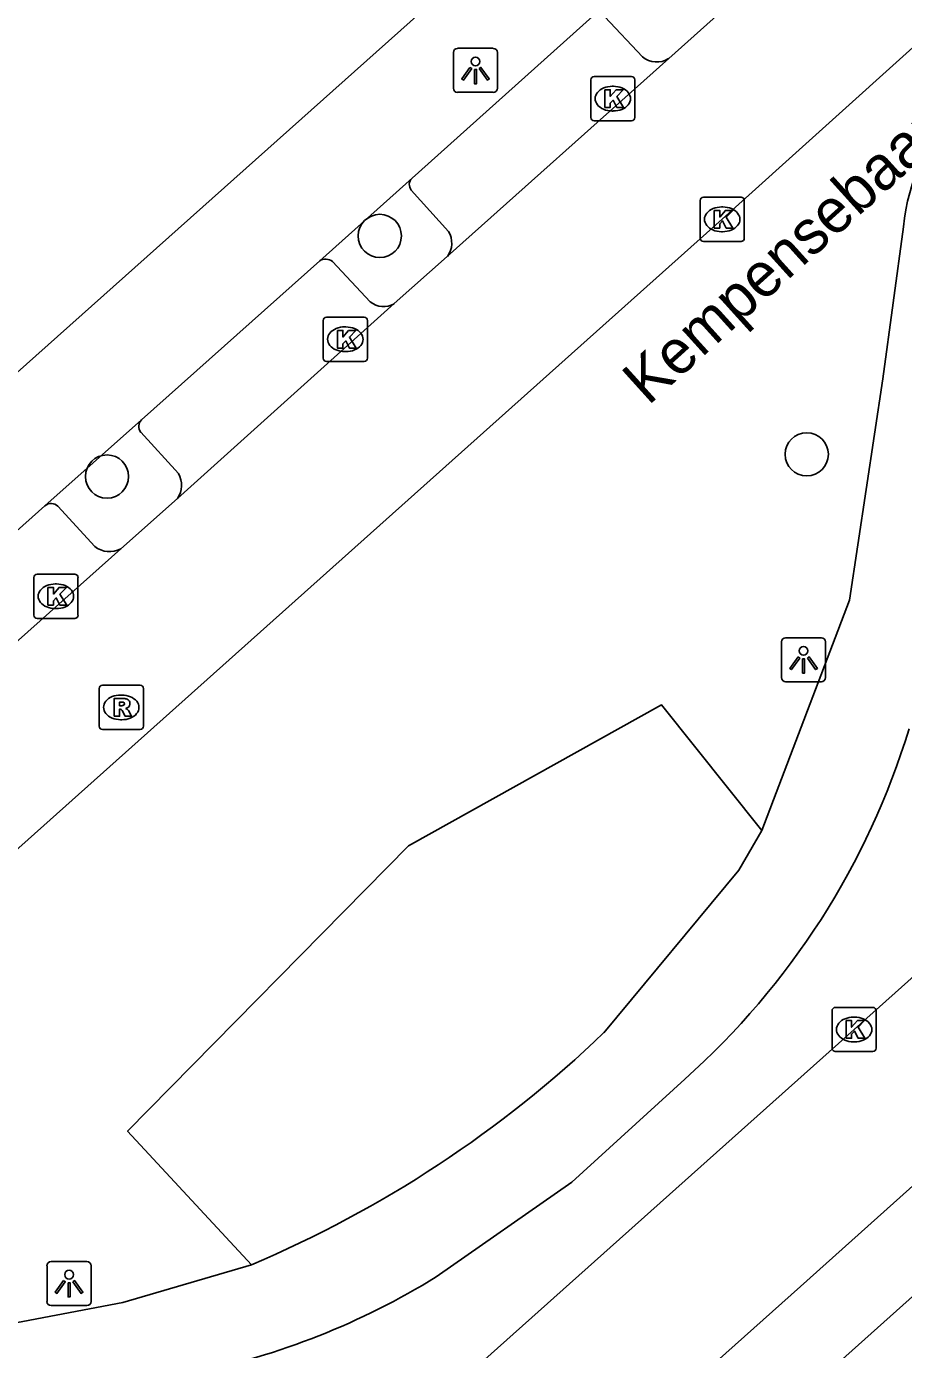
# Model space of a CAD drawing. Extents: x 162172 to 163187, y 382874 to 383684.
# Drawn here: x 162616.09 to 162635.94, y 383205.06 to 383235.01 of the extents above; entities that cross this region are included whole.
import ezdxf

# ---------------------------------------------------------------- set-up
doc = ezdxf.new("R2010")
doc.units = 0
for name, color, linetype in [('IMGEO_Berm_groen', 7, 'Continuous'), ('IMGEO_Boom', 7, 'Continuous'), ('IMGEO_Kolk', 7, 'Continuous'), ('IMGEO_Lichtpunt', 7, 'Continuous'), ('IMGEO_Openbare_ruimte_label', 7, 'Continuous'), ('IMGEO_Rijbaan_lokaal_open', 7, 'Continuous'), ('IMGEO_Rioolput', 7, 'Continuous'), ('IMGEO_Voetpad_gesloten', 7, 'Continuous'), ('IMGEO_Voetpad_open', 7, 'Continuous')]:
    doc.layers.add(name, color=color, linetype=linetype)

msp = doc.modelspace()

# ---------------------------------------------------------------- linework, layer by layer
at = {"layer": 'IMGEO_Berm_groen'}
msp.add_lwpolyline([(162632.733, 383216.809), (162630.462, 383219.659), (162624.74, 383216.468), (162618.378, 383210.002), (162621.186, 383206.981)], dxfattribs=at)
at = {"layer": 'IMGEO_Boom'}
for centre in [(162624.089, 383230.272), (162633.752, 383225.328), (162617.914, 383224.825)]:
    msp.add_circle(centre, 0.489, dxfattribs=at)
at = {"layer": 'IMGEO_Kolk'}
for p, q in [((162628.862, 383232.954), (162628.862, 383233.806)), ((162628.937, 383233.88), (162629.789, 383233.88)), ((162629.863, 383233.806), (162629.863, 383232.954)), ((162629.35, 383233.66), (162629.375, 383233.66)), ((162629.373, 383233.1), (162629.348, 383233.1)), ((162629.789, 383232.88), (162628.937, 383232.88)), ((162631.413, 383231.148), (162632.265, 383231.148)), ((162631.338, 383230.222), (162631.338, 383231.074)), ((162631.826, 383230.928), (162631.851, 383230.928)), ((162632.339, 383231.074), (162632.339, 383230.222)), ((162631.849, 383230.368), (162631.824, 383230.368)), ((162632.265, 383230.148), (162631.413, 383230.148)), ((162622.883, 383228.433), (162623.735, 383228.433)), ((162622.808, 383227.507), (162622.808, 383228.359)), ((162623.296, 383228.213), (162623.321, 383228.213)), ((162623.809, 383228.359), (162623.809, 383227.507)), ((162623.319, 383227.653), (162623.294, 383227.653)), ((162623.735, 383227.433), (162622.883, 383227.433)), ((162616.256, 383221.688), (162616.256, 383222.54)), ((162616.331, 383222.614), (162617.183, 383222.614)), ((162617.257, 383222.54), (162617.257, 383221.688)), ((162616.744, 383222.394), (162616.769, 383222.394)), ((162616.767, 383221.834), (162616.742, 383221.834)), ((162617.183, 383221.614), (162616.331, 383221.614)), ((162634.324, 383211.882), (162634.324, 383212.734)), ((162634.399, 383212.808), (162635.251, 383212.808)), ((162634.812, 383212.588), (162634.837, 383212.588)), ((162635.325, 383212.734), (162635.325, 383211.882)), ((162634.835, 383212.028), (162634.81, 383212.028)), ((162635.251, 383211.808), (162634.399, 383211.808))]:
    msp.add_line(p, q, dxfattribs=at)
for points in [[(162628.862, 383232.954), (162628.862, 383233.806)], [(162628.937, 383233.88), (162629.789, 383233.88)], [(162629.863, 383233.806), (162629.863, 383232.954)], [(162629.183, 383233.58), (162629.306, 383233.58), (162629.306, 383233.429), (162629.436, 383233.58), (162629.6, 383233.58), (162629.454, 383233.429), (162629.607, 383233.18), (162629.455, 383233.18), (162629.37, 383233.344), (162629.306, 383233.277), (162629.306, 383233.18), (162629.183, 383233.18), (162629.183, 383233.58)], [(162629.789, 383232.88), (162628.937, 383232.88)], [(162631.413, 383231.148), (162632.265, 383231.148)], [(162631.338, 383230.222), (162631.338, 383231.074)], [(162631.659, 383230.848), (162631.782, 383230.848), (162631.782, 383230.697), (162631.912, 383230.848), (162632.076, 383230.848), (162631.93, 383230.697), (162632.083, 383230.448), (162631.931, 383230.448), (162631.846, 383230.612), (162631.782, 383230.545), (162631.782, 383230.448), (162631.659, 383230.448), (162631.659, 383230.848)], [(162632.339, 383231.074), (162632.339, 383230.222)], [(162632.265, 383230.148), (162631.413, 383230.148)], [(162622.883, 383228.433), (162623.735, 383228.433)], [(162622.808, 383227.507), (162622.808, 383228.359)], [(162623.129, 383228.133), (162623.252, 383228.133), (162623.252, 383227.982), (162623.382, 383228.133), (162623.546, 383228.133), (162623.4, 383227.982), (162623.553, 383227.733), (162623.401, 383227.733), (162623.316, 383227.897), (162623.252, 383227.83), (162623.252, 383227.733), (162623.129, 383227.733), (162623.129, 383228.133)], [(162623.809, 383228.359), (162623.809, 383227.507)], [(162623.735, 383227.433), (162622.883, 383227.433)], [(162616.256, 383221.688), (162616.256, 383222.54)], [(162616.331, 383222.614), (162617.183, 383222.614)], [(162617.257, 383222.54), (162617.257, 383221.688)], [(162616.577, 383222.314), (162616.7, 383222.314), (162616.7, 383222.163), (162616.83, 383222.314), (162616.994, 383222.314), (162616.848, 383222.163), (162617.001, 383221.914), (162616.849, 383221.914), (162616.764, 383222.078), (162616.7, 383222.011), (162616.7, 383221.914), (162616.577, 383221.914), (162616.577, 383222.314)], [(162617.183, 383221.614), (162616.331, 383221.614)], [(162634.324, 383211.882), (162634.324, 383212.734)], [(162634.399, 383212.808), (162635.251, 383212.808)], [(162635.325, 383212.734), (162635.325, 383211.882)], [(162634.645, 383212.508), (162634.768, 383212.508), (162634.768, 383212.357), (162634.898, 383212.508), (162635.062, 383212.508), (162634.916, 383212.357), (162635.069, 383212.108), (162634.917, 383212.108), (162634.832, 383212.272), (162634.768, 383212.205), (162634.768, 383212.108), (162634.645, 383212.108), (162634.645, 383212.508)], [(162635.251, 383211.808), (162634.399, 383211.808)]]:
    msp.add_lwpolyline(points, dxfattribs=at)
for centre, start, end in [((162628.939, 383233.804), 91.552, 178.448), ((162628.939, 383233.804), 91.552, 178.448), ((162629.787, 383233.804), 1.552, 88.448), ((162629.787, 383233.804), 1.552, 88.448), ((162628.939, 383232.956), 181.552, 268.448), ((162628.939, 383232.956), 181.552, 268.448), ((162629.787, 383232.956), 271.552, 358.448), ((162629.787, 383232.956), 271.552, 358.448), ((162631.415, 383231.072), 91.552, 178.448), ((162631.415, 383231.072), 91.552, 178.448), ((162632.263, 383231.072), 1.552, 88.448), ((162632.263, 383231.072), 1.552, 88.448), ((162631.415, 383230.224), 181.552, 268.448), ((162631.415, 383230.224), 181.552, 268.448), ((162632.263, 383230.224), 271.552, 358.448), ((162632.263, 383230.224), 271.552, 358.448), ((162622.885, 383228.357), 91.552, 178.448), ((162622.885, 383228.357), 91.552, 178.448), ((162623.733, 383228.357), 1.552, 88.448), ((162623.733, 383228.357), 1.552, 88.448), ((162622.885, 383227.509), 181.552, 268.448), ((162622.885, 383227.509), 181.552, 268.448), ((162623.733, 383227.509), 271.552, 358.448), ((162623.733, 383227.509), 271.552, 358.448), ((162616.333, 383222.538), 91.552, 178.448), ((162616.333, 383222.538), 91.552, 178.448), ((162617.181, 383222.538), 1.552, 88.448), ((162617.181, 383222.538), 1.552, 88.448), ((162616.333, 383221.69), 181.552, 268.448), ((162616.333, 383221.69), 181.552, 268.448), ((162617.181, 383221.69), 271.552, 358.448), ((162617.181, 383221.69), 271.552, 358.448), ((162634.401, 383212.732), 91.552, 178.448), ((162634.401, 383212.732), 91.552, 178.448), ((162635.249, 383212.732), 1.552, 88.448), ((162635.249, 383212.732), 1.552, 88.448), ((162634.401, 383211.884), 181.552, 268.448), ((162634.401, 383211.884), 181.552, 268.448), ((162635.249, 383211.884), 271.552, 358.448), ((162635.249, 383211.884), 271.552, 358.448)]:
    msp.add_arc(centre, 0.0765, start, end, dxfattribs=at)
for centre, major_axis, ratio, start_param, end_param in [((162629.349, 383233.38), (-0.387, 0.002), 0.722429, 4.712389, 7.853982), ((162629.374, 383233.38), (-0.39, 0.002), 0.717154, 1.570796, 4.712389), ((162631.825, 383230.648), (-0.387, 0.002), 0.722429, 4.712389, 7.853982), ((162631.85, 383230.648), (-0.39, 0.002), 0.717154, 1.570796, 4.712389), ((162623.295, 383227.933), (-0.387, 0.002), 0.722429, 4.712389, 7.853982), ((162623.32, 383227.933), (-0.39, 0.002), 0.717154, 1.570796, 4.712389), ((162616.743, 383222.114), (-0.387, 0.002), 0.722429, 4.712389, 7.853982), ((162616.768, 383222.114), (-0.39, 0.002), 0.717154, 1.570796, 4.712389), ((162634.811, 383212.308), (-0.387, 0.002), 0.722429, 4.712389, 7.853982), ((162634.836, 383212.308), (-0.39, 0.002), 0.717154, 1.570796, 4.712389)]:
    msp.add_ellipse(centre, major_axis=major_axis, ratio=ratio, start_param=start_param, end_param=end_param, dxfattribs=at)
at = {"layer": 'IMGEO_Lichtpunt'}
for p, q in [((162625.755, 383234.424), (162625.755, 383233.617)), ((162625.755, 383234.424), (162625.755, 383233.617)), ((162626.657, 383234.519), (162625.849, 383234.519)), ((162626.657, 383234.519), (162625.849, 383234.519)), ((162626.751, 383233.617), (162626.751, 383234.424)), ((162626.751, 383233.617), (162626.751, 383234.424)), ((162625.849, 383233.523), (162626.657, 383233.523)), ((162625.849, 383233.523), (162626.657, 383233.523)), ((162633.181, 383221.081), (162633.181, 383220.274)), ((162633.181, 383221.081), (162633.181, 383220.274)), ((162634.083, 383221.176), (162633.275, 383221.176)), ((162634.083, 383221.176), (162633.275, 383221.176)), ((162634.177, 383220.274), (162634.177, 383221.081)), ((162634.177, 383220.274), (162634.177, 383221.081)), ((162633.275, 383220.18), (162634.083, 383220.18)), ((162633.275, 383220.18), (162634.083, 383220.18)), ((162616.556, 383206.959), (162616.556, 383206.152)), ((162616.556, 383206.959), (162616.556, 383206.152)), ((162617.458, 383207.054), (162616.65, 383207.054)), ((162617.458, 383207.054), (162616.65, 383207.054)), ((162617.552, 383206.152), (162617.552, 383206.959)), ((162617.552, 383206.152), (162617.552, 383206.959)), ((162616.65, 383206.058), (162617.458, 383206.058)), ((162616.65, 383206.058), (162617.458, 383206.058))]:
    msp.add_line(p, q, dxfattribs=at)
for points in [[(162626.129, 383234.088), (162626.168, 383234.06), (162625.98, 383233.798), (162625.942, 383233.825), (162626.129, 383234.088)], [(162626.231, 383234.04), (162626.278, 383234.04), (162626.278, 383233.718), (162626.231, 383233.718), (162626.231, 383234.04)], [(162626.341, 383234.06), (162626.379, 383234.087), (162626.566, 383233.825), (162626.527, 383233.797), (162626.341, 383234.06)], [(162633.555, 383220.745), (162633.594, 383220.717), (162633.406, 383220.455), (162633.368, 383220.482), (162633.555, 383220.745)], [(162633.657, 383220.697), (162633.704, 383220.697), (162633.704, 383220.375), (162633.657, 383220.375), (162633.657, 383220.697)], [(162633.767, 383220.717), (162633.805, 383220.744), (162633.992, 383220.482), (162633.953, 383220.454), (162633.767, 383220.717)], [(162616.93, 383206.623), (162616.969, 383206.595), (162616.781, 383206.333), (162616.743, 383206.36), (162616.93, 383206.623)], [(162617.032, 383206.575), (162617.079, 383206.575), (162617.079, 383206.253), (162617.032, 383206.253), (162617.032, 383206.575)], [(162617.142, 383206.595), (162617.18, 383206.622), (162617.367, 383206.36), (162617.328, 383206.332), (162617.142, 383206.595)]]:
    msp.add_lwpolyline(points, dxfattribs=at)
for centre in [(162626.254, 383234.222), (162633.68, 383220.879), (162617.055, 383206.757)]:
    msp.add_circle(centre, 0.0994, dxfattribs=at)
for centre, start, end in [((162625.849, 383234.424), 90, 180), ((162625.849, 383234.424), 90, 180), ((162626.657, 383234.424), 0, 90), ((162626.657, 383234.424), 0, 90), ((162625.849, 383233.617), 180, 270), ((162625.849, 383233.617), 180, 270), ((162626.657, 383233.617), 270, 0), ((162626.657, 383233.617), 270, 360), ((162633.275, 383221.081), 90, 180), ((162633.275, 383221.081), 90, 180), ((162634.083, 383221.081), 0, 90), ((162634.083, 383221.081), 0, 90), ((162633.275, 383220.274), 180, 270), ((162633.275, 383220.274), 180, 270), ((162634.083, 383220.274), 270, 0), ((162634.083, 383220.274), 270, 360), ((162616.65, 383206.959), 90, 180), ((162616.65, 383206.959), 90, 180), ((162617.458, 383206.959), 0, 90), ((162617.458, 383206.959), 0, 90), ((162616.65, 383206.152), 180, 270), ((162616.65, 383206.152), 180, 270), ((162617.458, 383206.152), 270, 0), ((162617.458, 383206.152), 270, 360)]:
    msp.add_arc(centre, 0.0946, start, end, dxfattribs=at)
at = {"layer": 'IMGEO_Rijbaan_lokaal_open'}
for points in [[(162594.538, 383197.307), (162598.429, 383200.785), (162614.417, 383215.084), (162631.839, 383230.648), (162640.771, 383238.704), (162646.358, 383243.687), (162663.821, 383259.29), (162676.816, 383270.908), (162691.32, 383283.864), (162708.036, 383298.826), (162711.785, 383302.188)], [(162694.039, 383265.267), (162682.786, 383255.183), (162664.524, 383238.887), (162648.558, 383224.594), (162634.825, 383212.308), (162621.087, 383200.028), (162606.584, 383187.068), (162604.928, 383185.572)], [(162633.717, 383237.061), (162630.627, 383234.286)], [(162630.627, 383234.286), (162625.617, 383229.807)], [(162625.617, 383229.807), (162624.414, 383228.739)], [(162624.414, 383228.739), (162619.513, 383224.33)], [(162617.125, 383191.769), (162633.608, 383206.492), (162653.433, 383224.25)], [(162619.513, 383224.33), (162618.227, 383223.191)], [(162618.227, 383223.191), (162608.746, 383214.728)]]:
    msp.add_lwpolyline(points, dxfattribs=at)
at = {"layer": 'IMGEO_Rioolput'}
for p, q in [((162617.811, 383220.099), (162618.663, 383220.099)), ((162617.736, 383219.173), (162617.736, 383220.025)), ((162618.224, 383219.879), (162618.249, 383219.879)), ((162618.737, 383220.025), (162618.737, 383219.173)), ((162618.247, 383219.319), (162618.222, 383219.319)), ((162618.663, 383219.099), (162617.811, 383219.099))]:
    msp.add_line(p, q, dxfattribs=at)
for points in [[(162617.811, 383220.099), (162618.663, 383220.099)], [(162617.736, 383219.173), (162617.736, 383220.025)], [(162618.325, 383219.797), (162618.073, 383219.799), (162618.073, 383219.399)], [(162618.737, 383220.025), (162618.737, 383219.173)], [(162618.073, 383219.399), (162618.197, 383219.399), (162618.197, 383219.561), (162618.208, 383219.561)], [(162618.251, 383219.718), (162618.197, 383219.718), (162618.197, 383219.637)], [(162618.197, 383219.637), (162618.249, 383219.637)], [(162618.255, 383219.532), (162618.326, 383219.399), (162618.466, 383219.399), (162618.401, 383219.525)], [(162618.663, 383219.099), (162617.811, 383219.099)]]:
    msp.add_lwpolyline(points, dxfattribs=at)
for centre, radius, start, end in [((162617.813, 383220.023), 0.0765, 91.552, 178.448), ((162617.813, 383220.023), 0.0765, 91.552, 178.448), ((162618.661, 383220.023), 0.0765, 1.552, 88.448), ((162618.661, 383220.023), 0.0765, 1.552, 88.448), ((162618.324, 383219.687), 0.109, 350.3612, 89.416), ((162618.207, 383219.508), 0.0533, 26.0293, 88.6989), ((162618.233, 383219.826), 0.19, 274.7715, 282.9687), ((162618.257, 383219.622), 0.0964, 77.0061, 93.1865), ((162618.271, 383219.679), 0.0378, 276.6634, 79.6772), ((162618.322, 383219.687), 0.112, 277.5842, 350.9817), ((162618.306, 383219.472), 0.108, 29.5134, 73.7905), ((162617.813, 383219.175), 0.0765, 181.552, 268.448), ((162617.813, 383219.175), 0.0765, 181.552, 268.448), ((162618.661, 383219.175), 0.0765, 271.552, 358.448), ((162618.661, 383219.175), 0.0765, 271.552, 358.448)]:
    msp.add_arc(centre, radius, start, end, dxfattribs=at)
for centre, major_axis, ratio, start_param, end_param in [((162618.223, 383219.599), (-0.387, 0.002), 0.722429, 4.712389, 7.853982), ((162618.248, 383219.599), (-0.39, 0.002), 0.717154, 1.570796, 4.712389)]:
    msp.add_ellipse(centre, major_axis=major_axis, ratio=ratio, start_param=start_param, end_param=end_param, dxfattribs=at)
at = {"layer": 'IMGEO_Voetpad_gesloten'}
for points in [[(162635.943, 383230.477), (162635.475, 383227.035), (162634.719, 383222.024), (162632.733, 383216.809)], [(162629.161, 383212.235), (162632.217, 383215.912), (162632.733, 383216.809)], [(162625.366, 383206.705), (162628.435, 383208.852), (162630.993, 383211.185)], [(162621.186, 383206.981), (162618.269, 383206.125), (162615.248, 383205.554)]]:
    msp.add_lwpolyline(points, dxfattribs=at)
for centre, radius, start, end in [((162640.815, 383229.991), 4.897, 137.7646, 174.2991), ((162619.346, 383224.234), 17.491, 311.7488, 342.9775), ((162610.879, 383231.306), 26.418, 292.9638, 313.7907), ((162616.436, 383221.22), 17.042, 281.5794, 301.5996)]:
    msp.add_arc(centre, radius, start, end, dxfattribs=at)
at = {"layer": 'IMGEO_Voetpad_open'}
for points in [[(162645.781, 383253.871), (162641.443, 383250), (162588.21, 383202.497), (162586.39, 383200.872)], [(162624.818, 383231.582), (162628.902, 383235.243)], [(162629.179, 383235.233), (162630.031, 383234.326)], [(162622.729, 383229.711), (162624.818, 383231.582)], [(162625.643, 383230.372), (162624.801, 383231.306)], [(162618.696, 383226.11), (162622.729, 383229.711)], [(162623.018, 383229.69), (162623.87, 383228.783)], [(162616.51, 383224.164), (162618.696, 383226.11)], [(162619.53, 383224.891), (162618.679, 383225.826)], [(162607.933, 383216.501), (162616.51, 383224.164)], [(162616.803, 383224.155), (162617.637, 383223.245)], [(162618.813, 383190.745), (162634.926, 383205.165), (162654.249, 383222.454)]]:
    msp.add_lwpolyline(points, dxfattribs=at)
for centre, radius, start, end in [((162630.357, 383234.726), 0.516, 230.8284, 301.4924), ((162624.96, 383231.435), 0.204, 133.8735, 219.0772), ((162625.212, 383230.109), 0.505, 323.3387, 31.3918), ((162622.858, 383229.49), 0.256, 51.3869, 120.301), ((162624.173, 383229.148), 0.475, 230.2922, 300.4595), ((162618.848, 383225.958), 0.215, 135.1549, 217.9939), ((162619.067, 383224.624), 0.534, 326.5851, 29.9435), ((162616.651, 383223.991), 0.224, 47.2914, 129.1898), ((162617.971, 383223.648), 0.524, 230.3215, 299.2196)]:
    msp.add_arc(centre, radius, start, end, dxfattribs=at)

# ---------------------------------------------------------------- texts
at = {"layer": 'IMGEO_Openbare_ruimte_label'}
msp.add_text('Kempensebaan', height=1, rotation=42.0809, dxfattribs=at).set_placement((162630.163, 383226.415))

doc.saveas('drawing.dxf')
